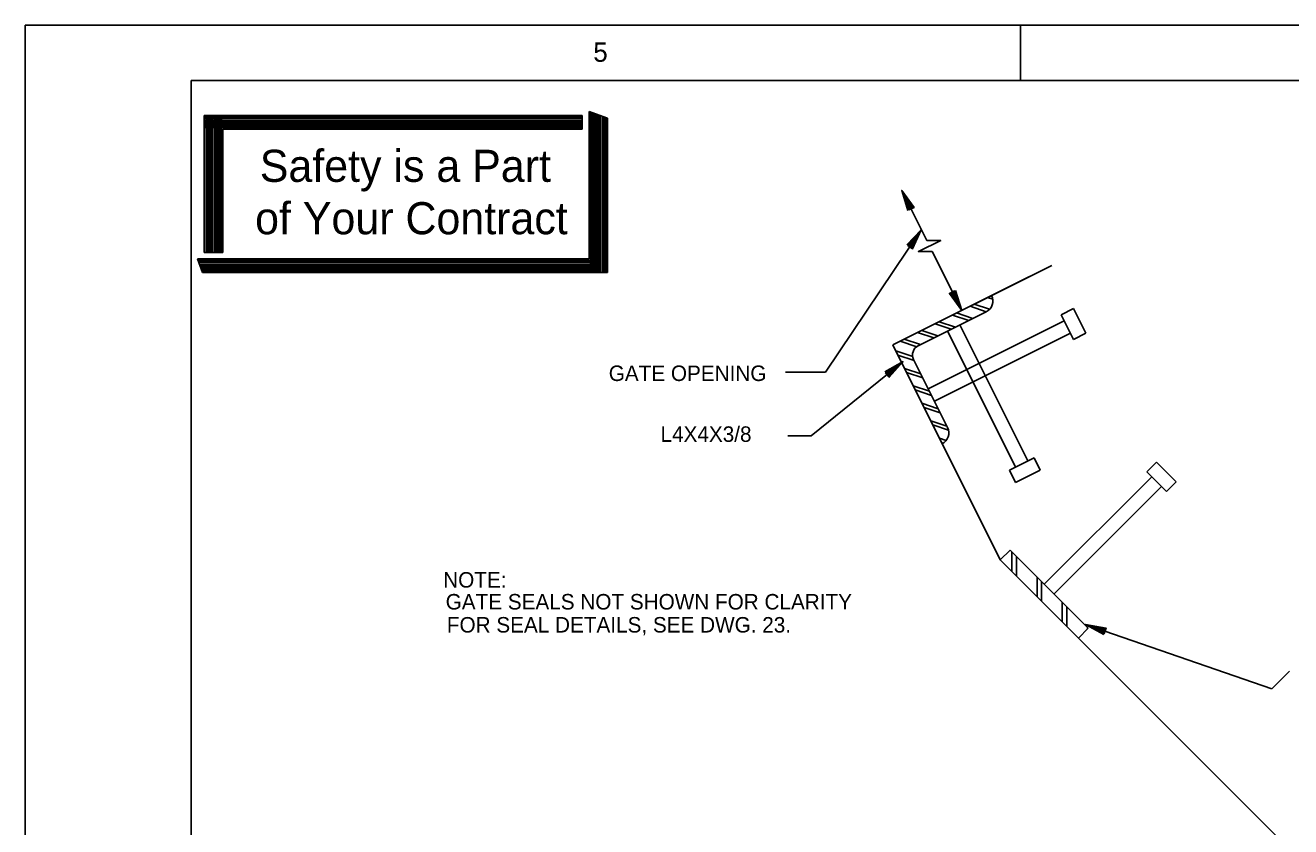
# Model space of a CAD drawing. Extents: x 0.1 to 13.5, y 0.1 to 9.5.
# Drawn here: x 0.124 to 3.938, y 7.04 to 9.457 of the extents above; entities that cross this region are included whole.
import ezdxf

# ---------------------------------------------------------------- set-up
doc = ezdxf.new("R2010")
doc.units = 0
for name, color, linetype in [('Level 1', 7, 'Continuous'), ('Level 13', 7, 'Continuous'), ('Level 2', 7, 'Continuous'), ('Level 25', 7, 'Continuous'), ('Level 3', 7, 'Continuous'), ('Level 36', 7, 'Continuous'), ('Level 50', 7, 'Continuous')]:
    doc.layers.add(name, color=color, linetype=linetype)

msp = doc.modelspace()

# ---------------------------------------------------------------- linework, layer by layer
at = {"layer": 'Level 1'}
for p, q in [((3.1238, 9.2903), (3.1238, 9.4569)), ((1.8234, 9.1973), (1.8234, 8.7527)), ((1.8234, 9.1973), (1.8791, 9.1767)), ((1.8271, 9.196), (1.8271, 8.711)), ((1.8321, 9.194), (1.8321, 8.711)), ((0.6634, 9.185), (1.8024, 9.185)), ((0.6634, 9.185), (0.6634, 8.7713)), ((0.6634, 9.1797), (1.8024, 9.1797)), ((0.6634, 9.1747), (1.8024, 9.1747)), ((0.6634, 9.1693), (1.8024, 9.1693)), ((0.6634, 9.164), (1.8024, 9.164)), ((0.6634, 9.159), (1.8024, 9.159)), ((0.6687, 9.185), (0.6687, 8.7713)), ((0.6737, 9.185), (0.6737, 8.7713)), ((0.6791, 9.185), (0.6791, 8.7713)), ((0.6841, 9.185), (0.6841, 8.7713)), ((0.6894, 9.185), (0.6894, 8.7713)), ((0.6947, 9.185), (0.6947, 8.7713)), ((0.6997, 9.185), (0.6997, 8.7713)), ((0.7051, 9.185), (0.7051, 8.7713)), ((0.7104, 9.185), (0.7104, 8.7713)), ((0.7154, 9.185), (0.7154, 8.7713)), ((1.8024, 9.185), (1.8024, 9.1433)), ((1.8374, 9.192), (1.8374, 8.711)), ((1.8427, 9.19), (1.8427, 8.711)), ((1.8477, 9.1883), (1.8477, 8.711)), ((1.8531, 9.1863), (1.8531, 8.711)), ((1.8581, 9.1843), (1.8581, 8.711)), ((1.8634, 9.1823), (1.8634, 8.711)), ((1.8687, 9.1807), (1.8687, 8.711)), ((1.8737, 9.1767), (1.8737, 8.711)), ((1.8791, 9.1767), (1.8791, 8.711)), ((0.6634, 9.1537), (1.8024, 9.1537)), ((0.6634, 9.1487), (1.8024, 9.1487)), ((0.7191, 9.1433), (1.8024, 9.1433)), ((0.7191, 9.1433), (0.7191, 8.7713)), ((0.6424, 8.7527), (1.8234, 8.7527)), ((0.6424, 8.7527), (0.6577, 8.711)), ((0.6444, 8.7473), (1.8271, 8.7473)), ((0.6461, 8.7423), (1.8271, 8.7423)), ((0.6481, 8.737), (1.8271, 8.737)), ((0.6634, 8.7713), (0.7191, 8.7713)), ((0.6501, 8.7317), (1.8271, 8.7317)), ((0.6521, 8.7267), (1.8271, 8.7267)), ((0.6541, 8.7213), (1.8271, 8.7213)), ((0.6557, 8.7163), (1.8271, 8.7163)), ((0.6577, 8.711), (1.8791, 8.711))]:
    msp.add_line(p, q, dxfattribs=at)
for points in [[(0.1238, 9.4569), (13.4571, 9.4569), (13.4571, 0.1236), (0.1238, 0.1236)], [(0.6238, 9.2903), (13.2904, 9.2903), (13.2904, 0.2903), (0.6238, 0.2903)]]:
    msp.add_lwpolyline(points, close=True, dxfattribs=at)
at = {"layer": 'Level 13'}
msp.add_lwpolyline([(2.8412, 8.8077), (2.8831, 8.8078), (2.8161, 8.7743), (2.8579, 8.7743)], dxfattribs=at)
at = {"layer": 'Level 2'}
for p, q in [((2.7656, 8.959), (2.8412, 8.8077)), ((2.9465, 8.597), (2.8579, 8.7743)), ((3.0981, 7.8093), (3.0981, 7.8683)), ((3.1115, 7.796), (3.1115, 7.8549)), ((3.174, 7.7335), (3.174, 7.7924)), ((3.1873, 7.7202), (3.1873, 7.7791)), ((3.2498, 7.6577), (3.2498, 7.7166)), ((3.2631, 7.6443), (3.2631, 7.7032)), ((3.3256, 7.6365), (3.3256, 7.6407))]:
    msp.add_line(p, q, dxfattribs=at)
at = {"layer": 'Level 25'}
for p, q in [((2.5355, 8.4104), (2.8248, 8.8406)), ((2.7386, 8.4931), (3.2184, 8.733)), ((2.7386, 8.4931), (3.1512, 8.6994)), ((3.0243, 8.6359), (3.0401, 8.6307)), ((3.0243, 8.6359), (3.0401, 8.6307)), ((2.9189, 8.5832), (2.9678, 8.5669)), ((2.9189, 8.5832), (2.9678, 8.5669)), ((2.9313, 8.5894), (2.9802, 8.5731)), ((2.9313, 8.5894), (2.9802, 8.5731)), ((2.9716, 8.6096), (3.0205, 8.5933)), ((2.9716, 8.6096), (3.0205, 8.5933)), ((2.984, 8.6158), (3.0301, 8.6004)), ((2.984, 8.6158), (3.0301, 8.6004)), ((3.2464, 8.5839), (3.2836, 8.6025)), ((2.8457, 8.3603), (3.2557, 8.5653)), ((2.8662, 8.5569), (2.9151, 8.5406)), ((2.8662, 8.5569), (2.9151, 8.5406)), ((2.8786, 8.5631), (2.9275, 8.5468)), ((2.8786, 8.5631), (2.9275, 8.5468)), ((2.9412, 8.5536), (3.1462, 8.1437)), ((2.7732, 8.5104), (2.8221, 8.4941)), ((2.7732, 8.5104), (2.8221, 8.4941)), ((2.8135, 8.5305), (2.8624, 8.5142)), ((2.8135, 8.5305), (2.8624, 8.5142)), ((2.8259, 8.5367), (2.8748, 8.5204)), ((2.8259, 8.5367), (2.8748, 8.5204)), ((2.8644, 8.323), (3.2743, 8.528)), ((2.904, 8.535), (3.1089, 8.125)), ((3.2836, 8.5093), (3.3209, 8.528)), ((2.7386, 8.4931), (3.0626, 7.8449)), ((2.7476, 8.475), (2.7988, 8.4579)), ((2.7476, 8.475), (2.7988, 8.4579)), ((2.7608, 8.5042), (2.8109, 8.4875)), ((2.7608, 8.5042), (2.8109, 8.4875)), ((2.7538, 8.4626), (2.8027, 8.4463)), ((2.7538, 8.4626), (2.8027, 8.4463)), ((2.4152, 8.4104), (2.5355, 8.4104)), ((2.774, 8.4223), (2.8229, 8.406)), ((2.774, 8.4223), (2.8229, 8.406)), ((2.7802, 8.4099), (2.8291, 8.3935)), ((2.7802, 8.4099), (2.8291, 8.3935)), ((2.8003, 8.3696), (2.8492, 8.3533)), ((2.8003, 8.3696), (2.8492, 8.3533)), ((2.8065, 8.3572), (2.8555, 8.3408)), ((2.8065, 8.3572), (2.8555, 8.3408)), ((2.8267, 8.3169), (2.8756, 8.3006)), ((2.8267, 8.3169), (2.8756, 8.3006)), ((2.8329, 8.3044), (2.8818, 8.2881)), ((2.853, 8.2642), (2.9019, 8.2479)), ((2.853, 8.2642), (2.9019, 8.2479)), ((2.8592, 8.2517), (2.9065, 8.236)), ((2.8592, 8.2517), (2.9065, 8.236)), ((2.8794, 8.2115), (2.8994, 8.2048)), ((2.8794, 8.2115), (2.8994, 8.2048)), ((2.8856, 8.199), (2.8911, 8.1972)), ((2.8856, 8.199), (2.8911, 8.1972)), ((3.1648, 8.153), (3.1834, 8.1157)), ((3.5046, 8.11), (3.534, 8.1395)), ((3.593, 8.0805), (3.534, 8.1395)), ((3.0903, 8.1157), (3.1089, 8.0785)), ((3.1952, 7.7712), (3.5193, 8.0953)), ((3.5635, 8.0511), (3.5046, 8.11)), ((3.2247, 7.7417), (3.5488, 8.0658)), ((3.5635, 8.0511), (3.593, 8.0805)), ((3.0626, 7.8449), (3.0921, 7.8743)), ((3.3278, 7.6386), (3.0921, 7.8743)), ((3.0627, 7.8448), (4.0694, 6.838)), ((3.2983, 7.6091), (3.3278, 7.6386)), ((3.8813, 7.4563), (3.9343, 7.5094))]:
    msp.add_line(p, q, dxfattribs=at)
at = {"layer": 'Level 3'}
for p, q in [((2.7565, 8.4318), (2.7565, 8.4318)), ((2.77, 8.4427), (2.77, 8.4427)), ((3.8813, 7.4563), (3.3196, 7.6499)), ((3.3196, 7.6499), (3.3196, 7.6499)), ((3.336, 7.6442), (3.336, 7.6442))]:
    msp.add_line(p, q, dxfattribs=at)
for points in [[(2.422, 8.2184), (2.4928, 8.2184), (2.77, 8.4427)], [(2.7151, 8.4115), (2.77, 8.4427), (2.7281, 8.3954), (2.7169, 8.4092), (2.7565, 8.4318), (2.728, 8.3997), (2.7209, 8.4085), (2.7436, 8.4213), (2.728, 8.404), (2.7251, 8.4076), (2.7301, 8.4104)], [(3.3751, 7.6198), (3.3196, 7.6499), (3.3819, 7.6393), (3.3761, 7.6226), (3.336, 7.6442), (3.3783, 7.6371), (3.3746, 7.6263), (3.3517, 7.6388), (3.3747, 7.6348), (3.3731, 7.6304), (3.3681, 7.6331)]]:
    msp.add_lwpolyline(points, dxfattribs=at)
at = {"layer": 'Level 36'}
for p, q in [((2.7386, 8.4931), (3.0367, 8.6421)), ((2.7386, 8.4931), (3.0367, 8.6421)), ((3.0204, 8.5932), (2.8155, 8.4907)), ((3.2464, 8.5839), (3.2836, 8.5093)), ((3.2836, 8.6025), (3.3209, 8.528)), ((2.8876, 8.1949), (2.7386, 8.4931)), ((2.8876, 8.1949), (2.7386, 8.4931)), ((2.8015, 8.4488), (2.9039, 8.2438)), ((3.1648, 8.153), (3.0903, 8.1157)), ((3.1834, 8.1157), (3.1089, 8.0785))]:
    msp.add_line(p, q, dxfattribs=at)
for centre, radius, start, end in [((3.0041, 8.6258), 0.0365, 296.5616, 26.5616), ((2.8294, 8.4628), 0.0313, 116.5616, 206.5616), ((2.8713, 8.2275), 0.0365, 296.5616, 26.5616)]:
    msp.add_arc(centre, radius, start, end, dxfattribs=at)
at = {"layer": 'Level 50'}
for p, q in [((2.7656, 8.959), (2.7656, 8.959)), ((2.7734, 8.9435), (2.7734, 8.9435)), ((2.8151, 8.8262), (2.8151, 8.8262)), ((2.8248, 8.8406), (2.8248, 8.8406)), ((2.9388, 8.6125), (2.9388, 8.6125)), ((2.9465, 8.597), (2.9465, 8.597))]:
    msp.add_line(p, q, dxfattribs=at)
for points in [[(2.7842, 8.8986), (2.7656, 8.959), (2.8027, 8.9079), (2.7869, 8.9), (2.7734, 8.9435), (2.7985, 8.9088), (2.7884, 8.9037), (2.7808, 8.9286), (2.7944, 8.9097), (2.7902, 8.9076), (2.7886, 8.9131)], [(2.7814, 8.7946), (2.8248, 8.8406), (2.7986, 8.7831), (2.7839, 8.7929), (2.8151, 8.8262), (2.7973, 8.7871), (2.7879, 8.7935), (2.8058, 8.8124), (2.796, 8.7912), (2.7922, 8.7938), (2.7962, 8.798)], [(2.9279, 8.6574), (2.9465, 8.597), (2.9094, 8.6482), (2.9252, 8.6561), (2.9388, 8.6125), (2.9136, 8.6473), (2.9237, 8.6524), (2.9313, 8.6275), (2.9178, 8.6464), (2.9219, 8.6485), (2.9236, 8.643)]]:
    msp.add_lwpolyline(points, dxfattribs=at)

# ---------------------------------------------------------------- texts
at = {"layer": 'Level 1'}
for s, height, p in [('5', 0.0584, (1.836, 9.3469)), ('Safety is a Part', 0.096792, (0.8306, 8.9848)), ('of Your Contract', 0.096792, (0.8165, 8.8268))]:
    msp.add_text(s, height=height, dxfattribs=at).set_placement(p)
at = {"layer": 'Level 2'}
for s, height, p in [('GATE OPENING', 0.046698, (1.8825, 8.3842)), ('L4X4X3/8', 0.0467, (2.0386, 8.2007)), ('NOTE:', 0.0467, (1.3835, 7.7612)), ('GATE SEALS NOT SHOWN FOR CLARITY', 0.046698, (1.3909, 7.6952)), ('FOR SEAL DETAILS, SEE DWG. 23.', 0.046698, (1.3945, 7.6257))]:
    msp.add_text(s, height=height, dxfattribs=at).set_placement(p)

doc.saveas('drawing.dxf')
